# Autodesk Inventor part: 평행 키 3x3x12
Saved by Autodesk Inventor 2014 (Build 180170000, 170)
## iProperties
Created: 2025-10
Part Number: 평행 키 3x3x12
Material: 일반
Document SubType Name: Modeling
Designer: dg
Density: 1 g/cm^3
Appearance: 기본값
Author: dg
Author: jhkim
Description: 키 및 해당 키홈
Creation Date: 2025-10-01
Sending System: Autodesk Inventor 2026
Preprocessor: ST-DEVELOPER v20.1
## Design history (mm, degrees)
node "평행 키 3x3x121"
body "Solid1"
node "기준1"
